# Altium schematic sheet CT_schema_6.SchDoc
size 479 x 328 mm
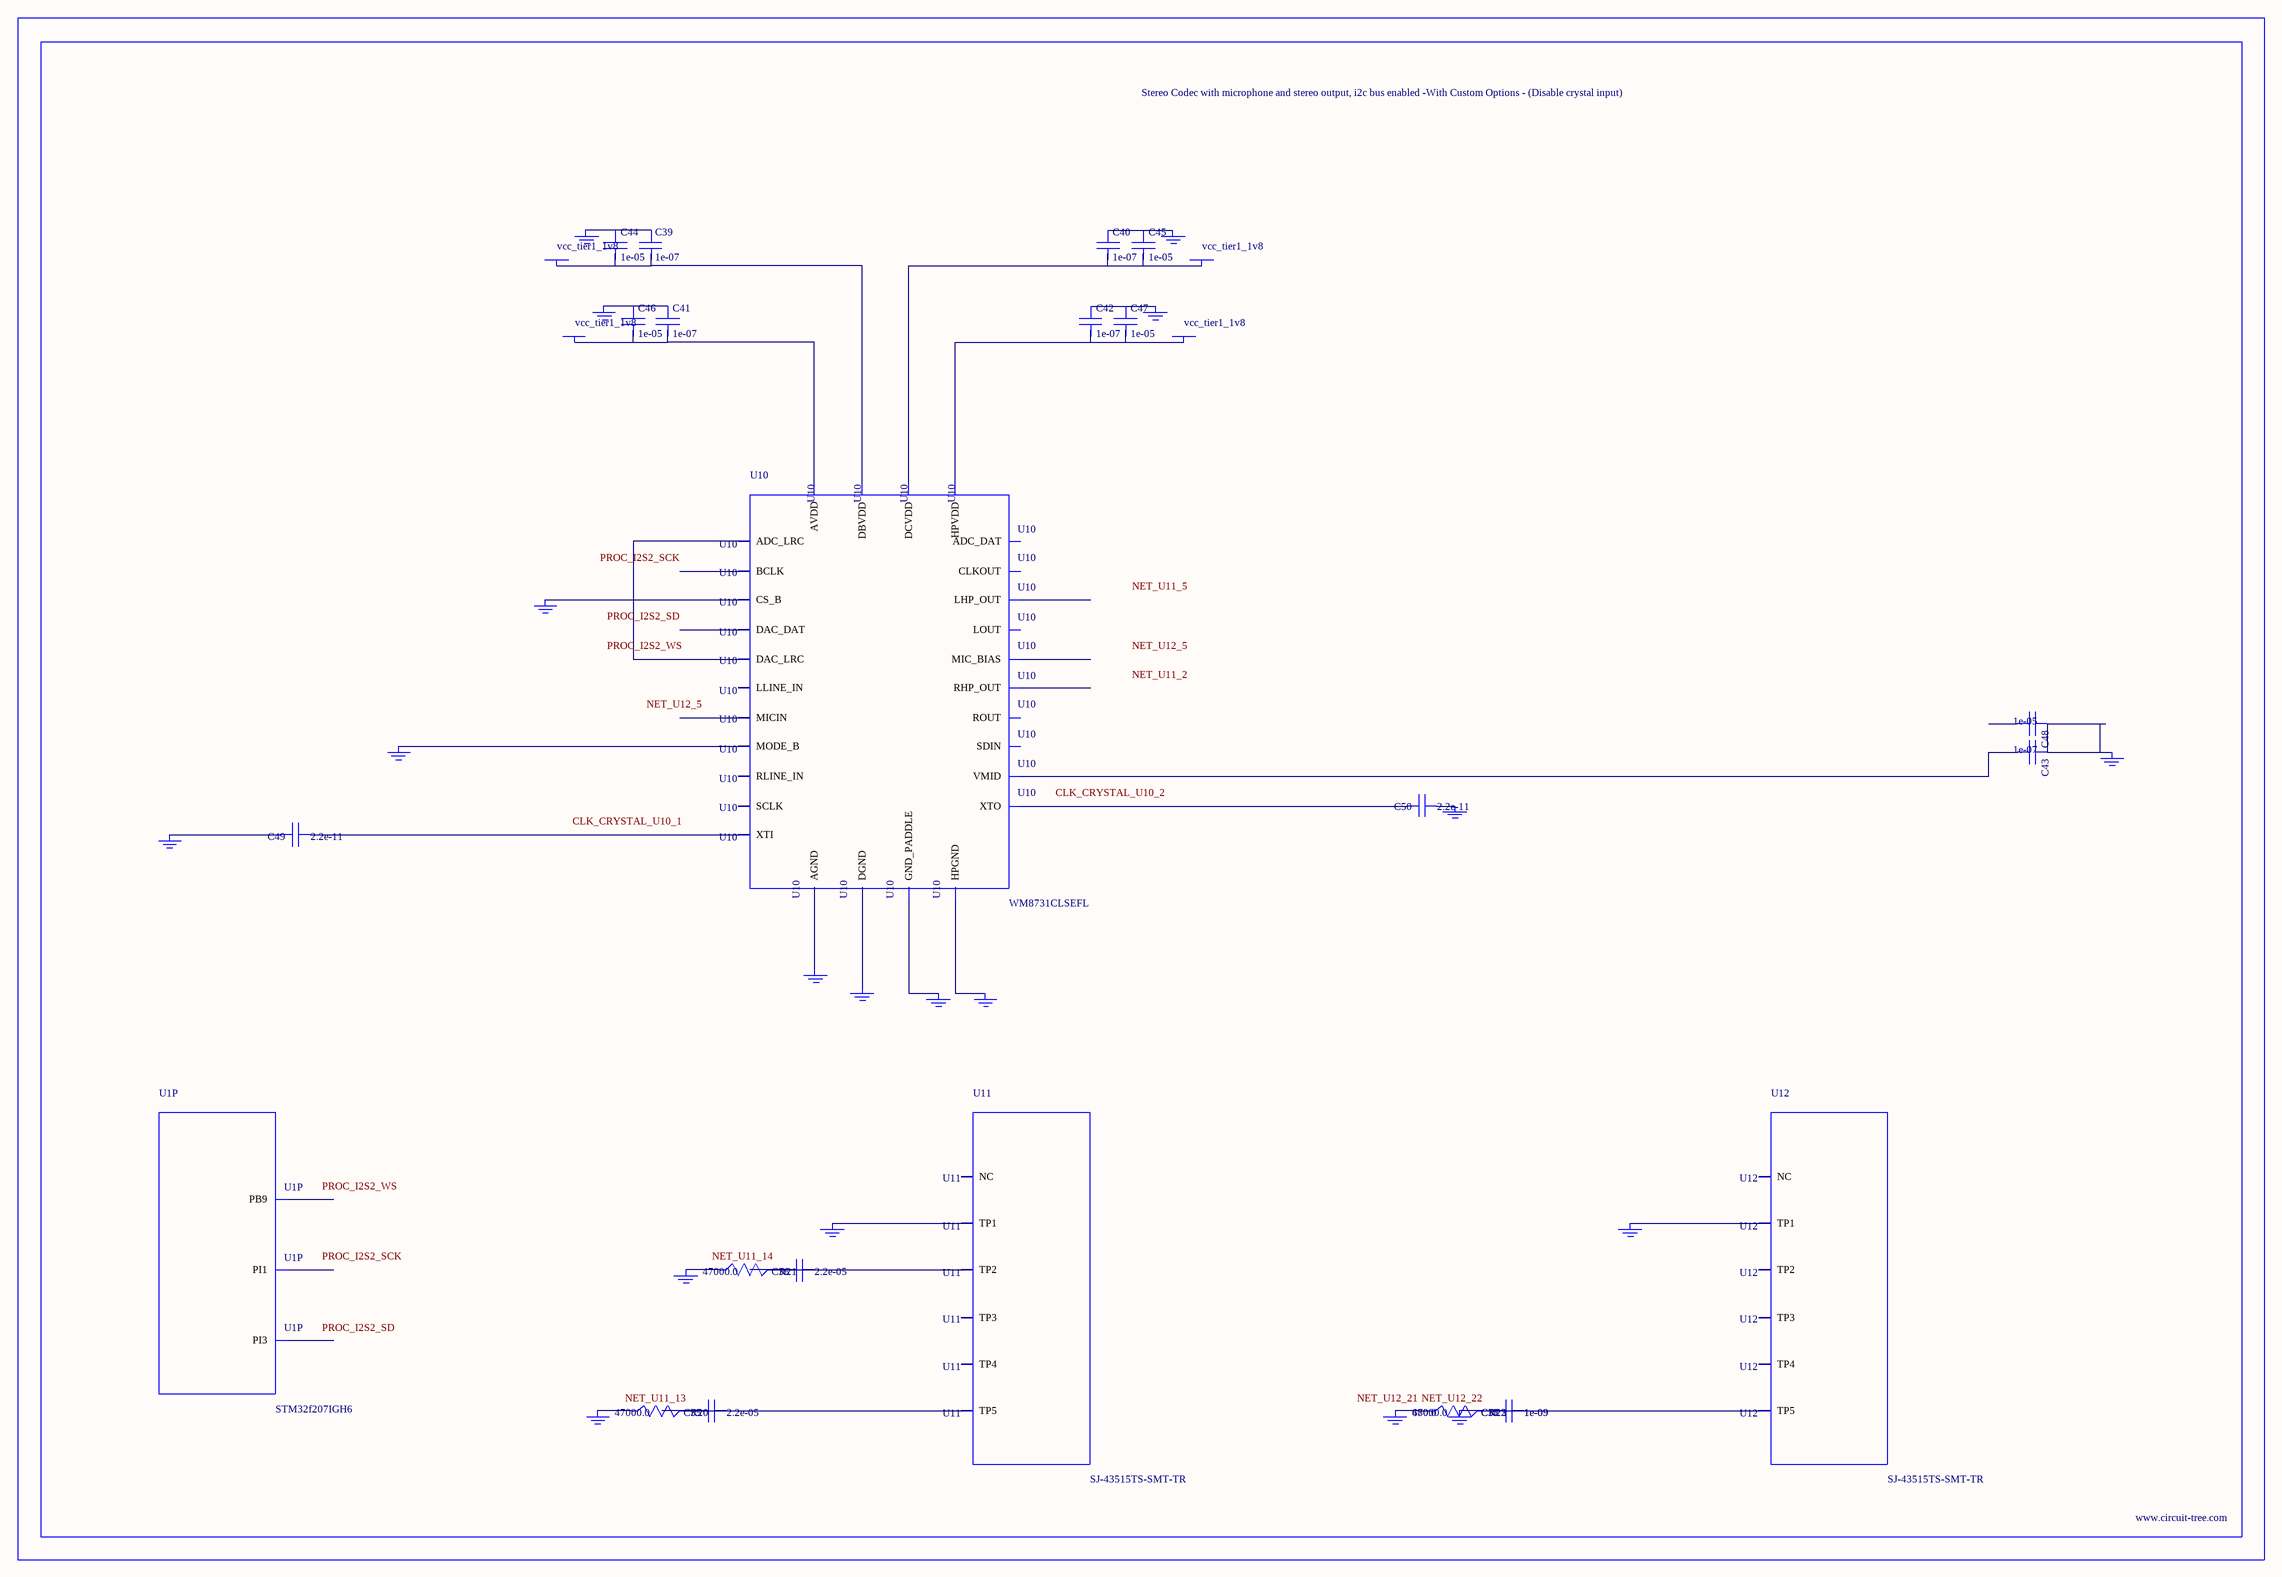
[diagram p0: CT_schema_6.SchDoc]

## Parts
BORDER5  (no value)
C35  2.2e-05  [C1210]
C36  2.2e-05  [C1210]
C37  1e-09  [C0402]
C38  1e-09  [C0402]
C39  1e-07  [C0402]
C40  1e-07  [C0402]
C41  1e-07  [C0402]
C42  1e-07  [C0402]
C43  1e-07  [C0402]
C44  1e-05  [C0805]
C45  1e-05  [C0805]
C46  1e-05  [C0805]
C47  1e-05  [C0805]
C48  1e-05  [C0805]
C49  2.2e-11  [C0402]
C50  2.2e-11  [C0402]
GND_INSTANCE_5_0  (no value)
GND_INSTANCE_5_1  (no value)
GND_INSTANCE_5_2  (no value)
GND_INSTANCE_5_3  (no value)
GND_INSTANCE_5_4  (no value)
GND_INSTANCE_5_5  (no value)
GND_INSTANCE_5_6  (no value)
GND_INSTANCE_5_7  (no value)
GND_INSTANCE_5_8  (no value)
GND_INSTANCE_5_9  (no value)
GND_INSTANCE_5_10  (no value)
GND_INSTANCE_5_11  (no value)
GND_INSTANCE_5_12  (no value)
GND_INSTANCE_5_13  (no value)
GND_INSTANCE_5_14  (no value)
GND_INSTANCE_5_15  (no value)
GND_INSTANCE_5_16  (no value)
GND_INSTANCE_5_17  (no value)
GND_INSTANCE_5_18  (no value)
POWER_INSTANCE_5_0  vcc_tier1_1v8
POWER_INSTANCE_5_1  vcc_tier1_1v8
POWER_INSTANCE_5_2  vcc_tier1_1v8
POWER_INSTANCE_5_3  vcc_tier1_1v8
R20  47000.0  [R0603]
R21  47000.0  [R0603]
R22  47000.0  [R0603]
R23  680.0  [R0603]
U1  STM32f207IGH6  [UFBGA176_25]  (part P of 16)
U10  WM8731CLSEFL  [QFN-28]
U11  SJ-43515TS-SMT-TR  [SJ-43515TS-SMT-TR]
U12  SJ-43515TS-SMT-TR  [SJ-43515TS-SMT-TR]

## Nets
NetC35_1: C35.1 C35.2 R20.2 U11.5(TP5)
NetC36_1: C36.1 C36.2 R21.2 U11.2(TP2)
NetC37_1: C37.1 C37.2 C38.1 C38.2 GND_INSTANCE_5_18.0(GND) R22.2 R23.2 U12.5(TP5)
NetC39_1: C39.1 C44.1 GND_INSTANCE_5_3.0(GND)
NetC39_2: C39.2 C44.2 POWER_INSTANCE_5_1.0(PWR) U10.5(DBVDD)
NetC40_1: C40.1 C45.1 GND_INSTANCE_5_2.0(GND)
NetC40_2: C40.2 C45.2 POWER_INSTANCE_5_0.0(PWR) U10.3(DCVDD)
NetC41_1: C41.1 C46.1 GND_INSTANCE_5_6.0(GND)
NetC41_2: C41.2 C46.2 POWER_INSTANCE_5_3.0(PWR) U10.18(AVDD)
NetC42_1: C42.1 C47.1 GND_INSTANCE_5_4.0(GND)
NetC42_2: C42.2 C47.2 POWER_INSTANCE_5_2.0(PWR) U10.12(HPVDD)
NetC43_1: C43.1 C48.1 GND_INSTANCE_5_7.0(GND)
NetC43_2: C43.2 U10.20(VMID)
NetC49_1: C49.1 U10.1(XTI)
NetC49_2: C49.2 GND_INSTANCE_5_0.0(GND)
NetC50_1: C50.1 GND_INSTANCE_5_1.0(GND)
NetC50_2: C50.2 U10.2(XTO)
NetGND_INSTANCE_5_5_0: GND_INSTANCE_5_5.0(GND) U10.15(HPGND)
NetGND_INSTANCE_5_8_0: GND_INSTANCE_5_8.0(GND) U10.25(MODE_B)
NetGND_INSTANCE_5_9_0: GND_INSTANCE_5_9.0(GND) U10.26(CS_B)
NetGND_INSTANCE_5_10_0: GND_INSTANCE_5_10.0(GND) U10.29(GND_PADDLE)
NetGND_INSTANCE_5_11_0: GND_INSTANCE_5_11.0(GND) U10.4(DGND)
NetGND_INSTANCE_5_12_0: GND_INSTANCE_5_12.0(GND) U10.19(AGND)
NetGND_INSTANCE_5_13_0: GND_INSTANCE_5_13.0(GND) U11.1(TP1)
NetGND_INSTANCE_5_14_0: GND_INSTANCE_5_14.0(GND) R21.1
NetGND_INSTANCE_5_15_0: GND_INSTANCE_5_15.0(GND) R20.1
NetGND_INSTANCE_5_16_0: GND_INSTANCE_5_16.0(GND) U12.1(TP1)
NetGND_INSTANCE_5_17_0: GND_INSTANCE_5_17.0(GND) R22.1 R23.1
NetU10_9: U10.9(DAC_LRC) U10.11(ADC_LRC)

Not connected (* = marked no-connect by the designer): C48 2; U1 B4(PB9) C13(PI3) D14(PI1); U10 6(CLKOUT) 7(BCLK) 8(DAC_DAT) 10(ADC_DAT) 13(LHP_OUT) 14(RHP_OUT) 16(LOUT) 17(ROUT) 21(MIC_BIAS) 22(MICIN) 23(RLINE_IN) 24(LLINE_IN) 27(SDIN) 28(SCLK); U11 3(TP3) 4(TP4) 6(NC); U12 2(TP2) 3(TP3) 4(TP4) 6(NC)

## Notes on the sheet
- Labels drawn without touching a wire or pin: CLK_CRYSTAL_U10_1, CLK_CRYSTAL_U10_2, NET_U11_2, NET_U11_5, NET_U11_13, NET_U11_14, NET_U12_5, NET_U12_21, NET_U12_22, PROC_I2S2_SCK, PROC_I2S2_SD, PROC_I2S2_WS

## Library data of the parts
BORDER5 = BORDER_PAGE5
C35 C36 = C1210C224K5RACTU
C37 C38 = C0402C102K3RAC
C39-C43 = C0402C104K3RACTU
C44-C48 = C0805C106K8RACTU
C49 C50 = C0402C220K3RAC
GND_INSTANCE_5_0-GND_INSTANCE_5_18 = GND
POWER_INSTANCE_5_0-POWER_INSTANCE_5_3 = PWR
R20-R22 = RC0603JR-0747KL
R23 = RC0603JR-07680RL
